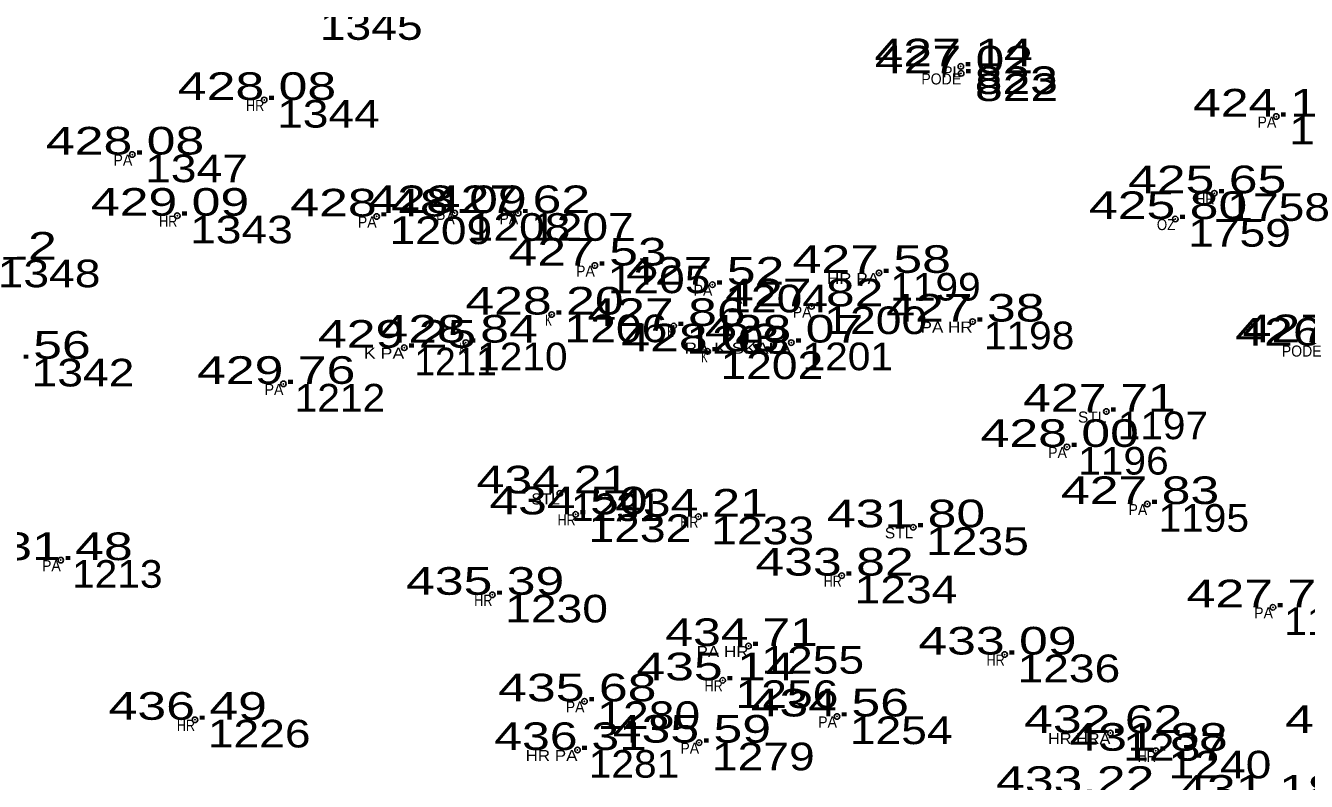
# Model space of a CAD drawing. Extents: x -639390 to -639074, y -1138747 to -1138358.
# Drawn here: x -639236.32 to -639201.57, y -1138624.12 to -1138603.62 of the extents above; entities that cross this region are included whole.
import ezdxf
from ezdxf.enums import TextEntityAlignment as Align

# ---------------------------------------------------------------- set-up
doc = ezdxf.new("R2010")
doc.units = 0
doc.header["$LTSCALE"] = 0.3
doc.header["$PDMODE"] = 32
doc.header["$PDSIZE"] = 0.15
for name, color, linetype in [('11', 7, 'Continuous'), ('12', 7, 'Continuous'), ('13', 7, 'Continuous'), ('57', 7, 'Continuous')]:
    doc.layers.add(name, color=color, linetype=linetype)

msp = doc.modelspace()

# ---------------------------------------------------------------- linework, layer by layer
at = {"layer": '11'}
for p in [(-639210.95, -1138604.73), (-639210.94, -1138604.92), (-639229.85, -1138605.64), (-639202.39, -1138606.09), (-639233.43, -1138607.12), (-639204.07, -1138608.17), (-639224.68, -1138608.71), (-639222.96, -1138608.71), (-639232.21, -1138608.78), (-639226.8, -1138608.8), (-639205.13, -1138608.87), (-639220.88, -1138610.13), (-639213.17, -1138610.33), (-639217.69, -1138610.65), (-639222.05, -1138611.46), (-639215, -1138611.24), (-639218.74, -1138611.77), (-639210.63, -1138611.65), (-639226.05, -1138612.36), (-639224.38, -1138612.22), (-639217.82, -1138612.46), (-639215.55, -1138612.22), (-639229.33, -1138613.34), (-639207, -1138614.09), (-639208.07, -1138615.05), (-639221.83, -1138616.31), (-639205.89, -1138616.6), (-639221.4, -1138616.88), (-639218.07, -1138616.94), (-639212.24, -1138617.23), (-639235.37, -1138618.12), (-639214.18, -1138618.54), (-639223.66, -1138619.06), (-639202.48, -1138619.4), (-639216.71, -1138620.45), (-639209.76, -1138620.68), (-639217.41, -1138621.38), (-639221.16, -1138621.95), (-639231.73, -1138622.45), (-639214.31, -1138622.36), (-639206.89, -1138622.81), (-639221.35, -1138623.27), (-639218.05, -1138623.07), (-639205.66, -1138623.29)]:
    msp.add_point(p, dxfattribs=at)

# ---------------------------------------------------------------- texts
at = {"layer": '12'}
for s, width, p in [('427.14 ', 1.4, (-639210.95, -1138604.73)), ('427.02 ', 1.4, (-639210.94, -1138604.92)), ('428.08 ', 1.4, (-639229.85, -1138605.64)), ('424.11 ', 1.35, (-639202.389, -1138606.09)), ('428.08 ', 1.4, (-639233.43, -1138607.12)), ('425.65 ', 1.4, (-639204.07, -1138608.17)), ('428.09 ', 1.4, (-639224.68, -1138608.71)), ('427.62 ', 1.4, (-639222.96, -1138608.71)), ('429.09 ', 1.4, (-639232.21, -1138608.78)), ('428.48 ', 1.4, (-639226.8, -1138608.8)), ('425.80 ', 1.4, (-639205.13, -1138608.87)), ('429.12 ', 1.4, (-639237.43, -1138609.97)), ('427.53 ', 1.4, (-639220.88, -1138610.13)), ('427.58 ', 1.4, (-639213.17, -1138610.33)), ('427.52 ', 1.4, (-639217.69, -1138610.65)), ('428.20 ', 1.4, (-639222.05, -1138611.46)), ('427.82 ', 1.4, (-639215, -1138611.24)), ('427.86 ', 1.4, (-639218.739, -1138611.77)), ('427.38 ', 1.4, (-639210.63, -1138611.65)), ('429.25 ', 1.4, (-639226.05, -1138612.36)), ('428.84 ', 1.4, (-639224.38, -1138612.22)), ('428.03 ', 1.4, (-639217.82, -1138612.46)), ('428.07 ', 1.4, (-639215.55, -1138612.22)), ('426.98 ', 1.4, (-639201.16, -1138612.3)), ('427.09 ', 1.4, (-639200.96, -1138612.21)), ('430.56 ', 1.4, (-639236.509, -1138612.66)), ('429.76 ', 1.4, (-639229.329, -1138613.34)), ('427.71 ', 1.35, (-639206.999, -1138614.09)), ('428.00 ', 1.4, (-639208.07, -1138615.05)), ('434.21 ', 1.35, (-639221.829, -1138616.31)), ('427.83 ', 1.4, (-639205.89, -1138616.6)), ('434.50 ', 1.4, (-639221.4, -1138616.88)), ('434.21 ', 1.35, (-639218.069, -1138616.94)), ('431.80 ', 1.4, (-639212.24, -1138617.23)), ('431.48 ', 1.4, (-639235.37, -1138618.12)), ('433.82 ', 1.4, (-639214.18, -1138618.54)), ('435.39 ', 1.4, (-639223.66, -1138619.06)), ('427.77 ', 1.4, (-639202.48, -1138619.4)), ('434.71 ', 1.35, (-639216.709, -1138620.45)), ('433.09 ', 1.4, (-639209.76, -1138620.68)), ('435.14 ', 1.4, (-639217.41, -1138621.38)), ('435.68 ', 1.4, (-639221.16, -1138621.95)), ('436.49 ', 1.4, (-639231.73, -1138622.45)), ('434.56 ', 1.4, (-639214.309, -1138622.36)), ('432.62 ', 1.4, (-639206.89, -1138622.81)), ('428.16 ', 1.4, (-639199.809, -1138622.81)), ('436.31 ', 1.35, (-639221.349, -1138623.27)), ('435.59 ', 1.4, (-639218.05, -1138623.07)), ('431.88 ', 1.4, (-639205.66, -1138623.29)), ('433.22 ', 1.4, (-639207.65, -1138624.46)), ('431.18 ', 1.4, (-639202.71, -1138624.7))]:
    msp.add_text(s, height=0.75, dxfattribs=dict(at, width=width)).set_placement(p, align=Align.CENTER)
at = {"layer": '13'}
for s, width, p in [(' 1345', 1.25, (-639228.69, -1138604.01)), (' 823', 1.35, (-639210.95, -1138605.48)), (' 822', 1.35, (-639210.94, -1138605.67)), (' 1344', 1.25, (-639229.85, -1138606.39)), (' 1757', 1.25, (-639202.39, -1138606.84)), (' 1347', 1.25, (-639233.43, -1138607.87)), (' 1758', 1.25, (-639204.07, -1138608.92)), (' 1343', 1.25, (-639232.21, -1138609.53)), (' 1209', 1.25, (-639226.8, -1138609.55)), (' 1208', 1.25, (-639224.68, -1138609.46)), (' 1207', 1.25, (-639222.96, -1138609.46)), (' 1759', 1.25, (-639205.13, -1138609.62)), (' 1348', 1.25, (-639237.43, -1138610.72)), (' 1205', 1.25, (-639220.88, -1138610.88)), (' 1199', 1.1, (-639213.17, -1138611.08)), (' 1204', 1.25, (-639217.69, -1138611.4)), (' 1200', 1.25, (-639215, -1138611.99)), (' 1206', 1.25, (-639222.05, -1138612.21)), (' 1203', 1.25, (-639218.74, -1138612.52)), (' 1198', 1.1, (-639210.63, -1138612.4)), (' 1210', 1.1, (-639224.38, -1138612.97)), (' 1202', 1.25, (-639217.82, -1138613.21)), (' 1201', 1.1, (-639215.55, -1138612.97)), (' 1342', 1.25, (-639236.51, -1138613.41)), (' 1212', 1.1, (-639229.33, -1138614.09)), (' 1197', 1.1, (-639207, -1138614.84)), (' 1196', 1.1, (-639208.07, -1138615.8)), (' 1231', 1.1, (-639221.83, -1138617.06)), (' 1195', 1.1, (-639205.89, -1138617.35)), (' 1232', 1.25, (-639221.4, -1138617.63)), (' 1233', 1.25, (-639218.07, -1138617.69)), (' 1235', 1.25, (-639212.24, -1138617.98)), (' 1213', 1.1, (-639235.37, -1138618.87)), (' 1234', 1.25, (-639214.18, -1138619.29)), (' 1230', 1.25, (-639223.66, -1138619.81)), (' 1194', 1.1, (-639202.48, -1138620.15)), (' 1255', 1.25, (-639216.71, -1138621.2)), (' 1236', 1.25, (-639209.76, -1138621.43)), (' 1256', 1.25, (-639217.41, -1138622.13)), (' 1280', 1.25, (-639221.16, -1138622.7)), (' 1226', 1.25, (-639231.73, -1138623.2)), (' 1254', 1.25, (-639214.31, -1138623.11)), (' 1237', 1.25, (-639206.89, -1138623.56)), (' 1281', 1.1, (-639221.35, -1138624.02)), (' 1279', 1.25, (-639218.05, -1138623.82)), (' 1240', 1.25, (-639205.66, -1138624.04))]:
    msp.add_text(s, height=0.75, dxfattribs=dict(at, width=width)).set_placement(p)
msp.add_text(' 1211', height=0.75, dxfattribs=at).set_placement((-639226.05, -1138613.11))
at = {"layer": '57'}
msp.add_text('PL', height=0.3, dxfattribs=at).set_placement((-639210.949, -1138605.03), align=Align.RIGHT)
for s, width, p in [('PODE', 0.95, (-639210.94, -1138605.22)), ('HR', 0.85, (-639229.849, -1138605.94)), ('PA', 0.95, (-639202.39, -1138606.39)), ('PA', 0.95, (-639233.43, -1138607.42)), ('HR', 0.85, (-639204.069, -1138608.47)), ('HR', 0.85, (-639232.209, -1138609.08)), ('PA', 0.95, (-639226.8, -1138609.1)), ('PA', 0.95, (-639224.68, -1138609.01)), ('PA', 0.95, (-639222.96, -1138609.01)), ('OZ', 0.9, (-639205.129, -1138609.17)), ('PA', 0.95, (-639220.88, -1138610.43)), ('HR PA', 1.15, (-639213.17, -1138610.63)), ('PA', 0.95, (-639217.69, -1138610.95)), ('PA', 0.95, (-639215, -1138611.54)), ('K', 0.65, (-639222.049, -1138611.76)), ('K', 0.65, (-639218.739, -1138612.07)), ('PA HR', 1.15, (-639210.629, -1138611.95)), ('K PA', 1.2, (-639226.05, -1138612.66)), ('K', 0.65, (-639224.379, -1138612.52)), ('PA K SKALA', 1.25, (-639215.55, -1138612.52)), ('K', 0.65, (-639217.819, -1138612.76)), ('PODE', 0.95, (-639201.16, -1138612.6)), ('PA', 0.95, (-639229.33, -1138613.64)), ('STL', 1.05, (-639206.999, -1138614.39)), ('PA', 0.95, (-639208.07, -1138615.35)), ('STL', 1.05, (-639221.829, -1138616.61)), ('PA', 0.95, (-639205.89, -1138616.9)), ('HR', 0.85, (-639221.399, -1138617.18)), ('HR', 0.85, (-639218.069, -1138617.24)), ('STL', 1.05, (-639212.239, -1138617.53)), ('PA', 0.95, (-639235.37, -1138618.42)), ('HR', 0.85, (-639214.179, -1138618.84)), ('HR', 0.85, (-639223.659, -1138619.36)), ('PA', 0.95, (-639202.48, -1138619.7)), ('PA HR', 1.15, (-639216.709, -1138620.75)), ('HR', 0.85, (-639209.759, -1138620.98)), ('HR', 0.85, (-639217.409, -1138621.68)), ('PA', 0.95, (-639221.16, -1138622.25)), ('HR', 0.85, (-639231.729, -1138622.75)), ('PA', 0.95, (-639214.31, -1138622.66)), ('HR HRA', 1.1, (-639206.89, -1138623.11)), ('PA', 0.95, (-639218.05, -1138623.37)), ('HR PA', 1.15, (-639221.35, -1138623.57)), ('HR', 0.85, (-639205.659, -1138623.59))]:
    msp.add_text(s, height=0.3, dxfattribs=dict(at, width=width)).set_placement(p, align=Align.RIGHT)

doc.saveas('drawing.dxf')
